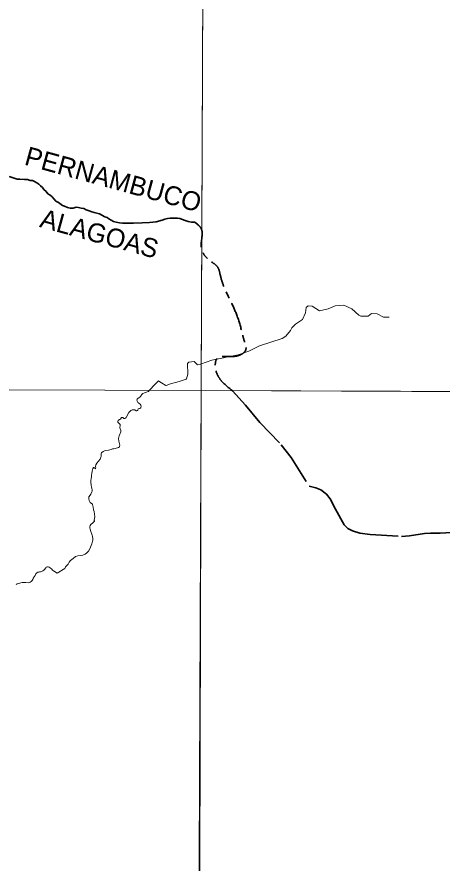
# Model space of a CAD drawing. Extents: x 553962 to 842807, y 8883888 to 9032388.
# Drawn here: x 595860 to 597659, y 8918990 to 8922569 of the extents above; entities that cross this region are included whole.
import ezdxf
from ezdxf.enums import TextEntityAlignment as Align

# ---------------------------------------------------------------- set-up
doc = ezdxf.new("R2010")
doc.units = 0
doc.header["$LTSCALE"] = 20
doc.linetypes.add('LONG_DASH_SHORT_DASH', pattern=[9.9, 6, -1.2, 1.5, -1.2])
doc.layers.add('6', color=7, linetype='Continuous', lineweight=13)

msp = doc.modelspace()

# ---------------------------------------------------------------- linework, layer by layer
at = {"layer": '6'}
for points in [[(585656.26, 8924738.82), (596655.53, 8924715.82), (596639.85, 8920989.8), (585645.85, 8921027.32)], [(607600.79, 8920952.39), (596639.85, 8920989.8), (596608.84, 8909934.36), (607569.77, 8909894.88)]]:
    msp.add_lwpolyline(points, close=True, dxfattribs=at)
for points in [[(596655.53, 8924715.82), (596593.31, 8909930.27), (596531.66, 8896026.67)], [(597434.32, 8921299.66), (597411.47, 8921299.66), (597383.8, 8921313.69), (597360.5, 8921314.54), (597345.55, 8921303.6), (597314.44, 8921304.05), (597306.5, 8921308.03), (597277.55, 8921334.74), (597243.27, 8921349.69), (597206.88, 8921347.93), (597176.84, 8921335.09), (597140.6, 8921326.89), (597109.42, 8921345.3), (597091.82, 8921347.04), (597083.97, 8921340.91), (597080.39, 8921317.92), (597067.69, 8921289.13), (597038.15, 8921270.09), (597022.53, 8921254.03), (597017.62, 8921243.42), (596998.37, 8921219.35), (596982.49, 8921209.19), (596886.23, 8921177.54), (596841.39, 8921155.35), (596795.95, 8921139.41), (596684.44, 8921117.89), (596636.53, 8921101.05), (596623.71, 8921097.86), (596609.86, 8921111.73), (596587.69, 8921108.95), (596581.16, 8921103.5)], [(596581.16, 8921103.5), (596583.43, 8921057.98), (596577.38, 8921038.4), (596576.5, 8921036.9), (596546.91, 8921026.83), (596509.13, 8921016.73), (596491.66, 8921010.28), (596489.99, 8921010.84), (596472.11, 8921022.26), (596460.66, 8921029.18), (596459.59, 8921029.55), (596457.73, 8921028.04), (596445.16, 8921015.39), (596419.45, 8920988.88)], [(574684.91, 8921064.73), (596639.85, 8920989.8), (607636.31, 8920937.24), (626625.69, 8920820.54)], [(596419.45, 8920988.88), (596416.12, 8920985.49), (596411.59, 8920983.06), (596407.81, 8920981.74), (596399.45, 8920979.98), (596392.68, 8920976.49), (596389.75, 8920974.18), (596389.37, 8920973.24), (596388.48, 8920972.85), (596387.99, 8920971.76), (596387, 8920970.83), (596385.52, 8920967.97), (596383.21, 8920964.49), (596380.2, 8920960.74), (596376.19, 8920958.12), (596372.52, 8920956.2), (596369.56, 8920953.63), (596368.37, 8920952), (596367.36, 8920948.27), (596368.09, 8920946.05), (596368.24, 8920944.4), (596369.98, 8920941.48), (596371.9, 8920939.11), (596374.24, 8920937.35), (596377.34, 8920934.49), (596380.95, 8920931.89), (596384.82, 8920927.52), (596384.82, 8920927.52), (596385.6, 8920924.64), (596383.91, 8920916.42), (596383.56, 8920915.61), (596379.67, 8920913.54), (596373.18, 8920911.78), (596371.32, 8920906.47), (596370.18, 8920904.36), (596367.56, 8920903.14), (596364.07, 8920903.5), (596358.31, 8920907.23), (596357.26, 8920907.53), (596352.76, 8920907.69), (596347.54, 8920907.08), (596342.58, 8920904.68), (596337.1, 8920900.01), (596333.05, 8920895.91), (596322.91, 8920878.19)], [(596322.91, 8920878.19), (596321.81, 8920875.49), (596320.46, 8920873.24), (596315.83, 8920871.41), (596312.59, 8920871.35), (596310.37, 8920872.67), (596308.43, 8920874.53), (596302.98, 8920874.92), (596298.09, 8920868.58), (596293.72, 8920866.1), (596288.49, 8920862.57), (596287.26, 8920858.09), (596287.34, 8920855.8), (596289.18, 8920853.14), (596295.67, 8920846.8), (596296.17, 8920845.8), (596296.8, 8920842.92), (596295.01, 8920831.97), (596300.21, 8920819.37), (596299.33, 8920813.81), (596292.37, 8920797.27), (596290.65, 8920791.71), (596289.42, 8920786.32), (596290.67, 8920775.02), (596292.34, 8920769.45), (596293.44, 8920763.89), (596295.28, 8920758.32), (596294.3, 8920752.94), (596293.45, 8920750.96), (596289.69, 8920748.17), (596275.61, 8920744.04), (596269.88, 8920743.11), (596264.49, 8920741.87), (596258.75, 8920739.72), (596253.19, 8920738.4), (596247.61, 8920736.72), (596236.49, 8920735.18), (596230.93, 8920733.69), (596225.37, 8920731.32), (596218.84, 8920726.46), (596218.18, 8920725.51), (596216.74, 8920722.18), (596215.76, 8920715.69), (596215.72, 8920710.13), (596215.3, 8920707.11), (596211.6, 8920699.16), (596197.66, 8920682.04), (596193.8, 8920675.42), (596193.08, 8920667.7), (596194.22, 8920664.14), (596192.85, 8920660.71), (596192.23, 8920658.07), (596192, 8920657.96), (596185.8, 8920663.46), (596183.34, 8920663.3), (596181.08, 8920659.84), (596179.35, 8920654.29), (596178.07, 8920648.73), (596176.79, 8920637.77), (596175.71, 8920632.03), (596175.21, 8920626.1), (596173.36, 8920615.34), (596172.72, 8920609.77), (596172.75, 8920603.59), (596174.44, 8920586.91), (596175.29, 8920581.1), (596177.17, 8920575.09), (596177.8, 8920569.48), (596177.63, 8920563.29), (596177.26, 8920559.99), (596173.24, 8920551.41), (596169.7, 8920545.99), (596164.45, 8920539.01), (596163.75, 8920534.68), (596164.37, 8920529.29), (596165.83, 8920523.47), (596169.82, 8920515.63), (596178.99, 8920508.32), (596179.73, 8920507.26), (596181.25, 8920501.89), (596182.16, 8920495.73), (596184.61, 8920484.29), (596186.47, 8920477.54), (596189.89, 8920455.39)], [(596189.89, 8920455.39), (596189.5, 8920454.3), (596187.16, 8920440.19), (596187.24, 8920439.42), (596188.29, 8920437.65), (596188.35, 8920437.13), (596185.53, 8920433.83), (596181.53, 8920430.19), (596172.41, 8920422.97), (596169.54, 8920418.82), (596168.25, 8920412.85), (596168.65, 8920407.71), (596169.47, 8920402.74), (596171.98, 8920392.66), (596176.53, 8920381.45), (596178.04, 8920376.88), (596179.15, 8920371.58), (596180.62, 8920361.12), (596180.59, 8920356.34), (596179.58, 8920351.37), (596176.69, 8920340.77), (596168.03, 8920320.05), (596162.52, 8920309.98), (596158.77, 8920305.41), (596153.65, 8920300.7), (596148.82, 8920297.31), (596144.01, 8920294.93), (596139.23, 8920293.32), (596128.61, 8920290.87), (596118.17, 8920289.71), (596108.23, 8920286.59), (596097.62, 8920278.64)], [(596097.62, 8920278.64), (596087.02, 8920270.68), (596086.21, 8920270.36), (596080.9, 8920262.79), (596078.5, 8920257.89), (596076.04, 8920254.38), (596072.41, 8920250.05), (596065.82, 8920243.22), (596064.14, 8920240.59), (596062.95, 8920236.21), (596030.01, 8920216.66), (596014.61, 8920225.89), (596013.72, 8920226.16), (596013.13, 8920226.79), (596012.78, 8920227.68), (596010.89, 8920229.43), (596007.87, 8920232.83), (596000.17, 8920239.67), (595996.74, 8920242.22), (595992.38, 8920243.51), (595988.72, 8920243.25), (595985.37, 8920242.5), (595983.71, 8920241.78), (595981.56, 8920239.61), (595976.38, 8920232.59), (595973.2, 8920229.42), (595969.3, 8920226.3), (595963.36, 8920223.64), (595959.66, 8920222.41), (595955.66, 8920221.9), (595951.96, 8920221.11), (595948.48, 8920221.06), (595947.69, 8920220.85), (595944.66, 8920218.59), (595940.47, 8920213.79), (595940.1, 8920212.71), (595939.1, 8920212.03), (595936.67, 8920206.92)], [(595936.67, 8920206.92), (595936.63, 8920206.91), (595929.07, 8920195.56), (595929.25, 8920192.4), (595927.79, 8920190.07), (595923.97, 8920185.53), (595919.53, 8920180.89), (595916.46, 8920178.5), (595912.41, 8920177.2), (595907.28, 8920176.15), (595897.18, 8920176.96), (595891.87, 8920177.8), (595886.38, 8920177.78), (595881.6, 8920177.17), (595866.19, 8920173.53), (595861.06, 8920171.8), (595856.25, 8920168.82)]]:
    msp.add_lwpolyline(points, dxfattribs=at)
at = {"layer": '6', "linetype": 'LONG_DASH_SHORT_DASH', "lineweight": 35}
for points in [[(595827.14, 8921893.77), (595861.33, 8921882.87), (595871.87, 8921882.92), (595892.46, 8921882.01), (595904.01, 8921881.06), (595916.08, 8921878.1), (595925.62, 8921877.14), (595934.67, 8921873.66), (595943.73, 8921867.18), (595952.29, 8921861.69), (595960.35, 8921855.2), (595968.41, 8921847.71), (595973.97, 8921838.7), (595983.54, 8921831.21), (595990.11, 8921821.7), (596000.17, 8921815.72), (596007.73, 8921809.23), (596016.81, 8921798.73), (596024.87, 8921790.73), (596035.44, 8921784.76), (596052.06, 8921771.78), (596061.61, 8921768.81), (596073.68, 8921763.34), (596085.24, 8921760.38), (596097.29, 8921760.44), (596110.33, 8921764.51), (596119.87, 8921763.55), (596131.44, 8921760.08), (596142.49, 8921759.13), (596153.55, 8921753.16), (596165.62, 8921749.7), (596176.68, 8921745.23), (596186.74, 8921741.76), (596208.85, 8921735.83), (596231.99, 8921724.39), (596241.55, 8921720.92), (596249.1, 8921714.93), (596268.72, 8921704.47), (596279.78, 8921701.01), (596294.35, 8921698.06), (596306.91, 8921697.11), (596319.97, 8921696.67), (596353.6, 8921696.82), (596389.24, 8921698.99), (596420.36, 8921700.13), (596448.47, 8921702.26), (596474.55, 8921709.41), (596486.08, 8921713.47), (596497.61, 8921717.04), (596508.15, 8921718.09), (596528.74, 8921718.18), (596538.78, 8921717.72), (596549.83, 8921716.27), (596560.39, 8921712.3), (596572.45, 8921708.84), (596585.03, 8921703.37), (596598.59, 8921701.42), (596611.63, 8921701.48)], [(596772.73, 8920987.62), (596827.15, 8920927.65), (596887.57, 8920854.37), (596978.34, 8920759.69), (597020.14, 8920705.34), (597096.59, 8920584.97), (597125.25, 8920577.05), (597146.47, 8920568.48), (597170.19, 8920550.21), (597184.87, 8920530.73), (597208.36, 8920486.66), (597244.58, 8920421.2), (597260.58, 8920405.58), (597280.5, 8920395.73), (597310.75, 8920386.44), (597353.94, 8920380.26), (597487.45, 8920372.01), (597521.03, 8920374.31), (597585, 8920384.08), (597610.19, 8920386.44), (597650.19, 8920385.45), (597721.85, 8920389.35)]]:
    msp.add_lwpolyline(points, dxfattribs=at)
msp.add_spline([(596611.23, 8921701.88), (596639.86, 8921673.24), (596639.86, 8921601.63), (596665.62, 8921547.21), (596711.43, 8921507.11), (596720.02, 8921478.47), (596734.33, 8921432.64), (596788.73, 8921312.33), (596811.63, 8921237.86), (596823.08, 8921194.9), (596828.81, 8921163.39), (596788.73, 8921134.75), (596705.7, 8921123.29), (596699.98, 8921083.19), (596772.73, 8920987.62)], degree=3, dxfattribs=at)

# ---------------------------------------------------------------- texts
at = {"layer": '6'}
for s, p in [('PERNAMBUCO', (596257.07, 8921844.04)), ('ALAGOAS', (596198.51, 8921614.14))]:
    msp.add_text(s, height=80, rotation=344.671, dxfattribs=at).set_placement(p, align=Align.CENTER)

doc.saveas('drawing.dxf')
